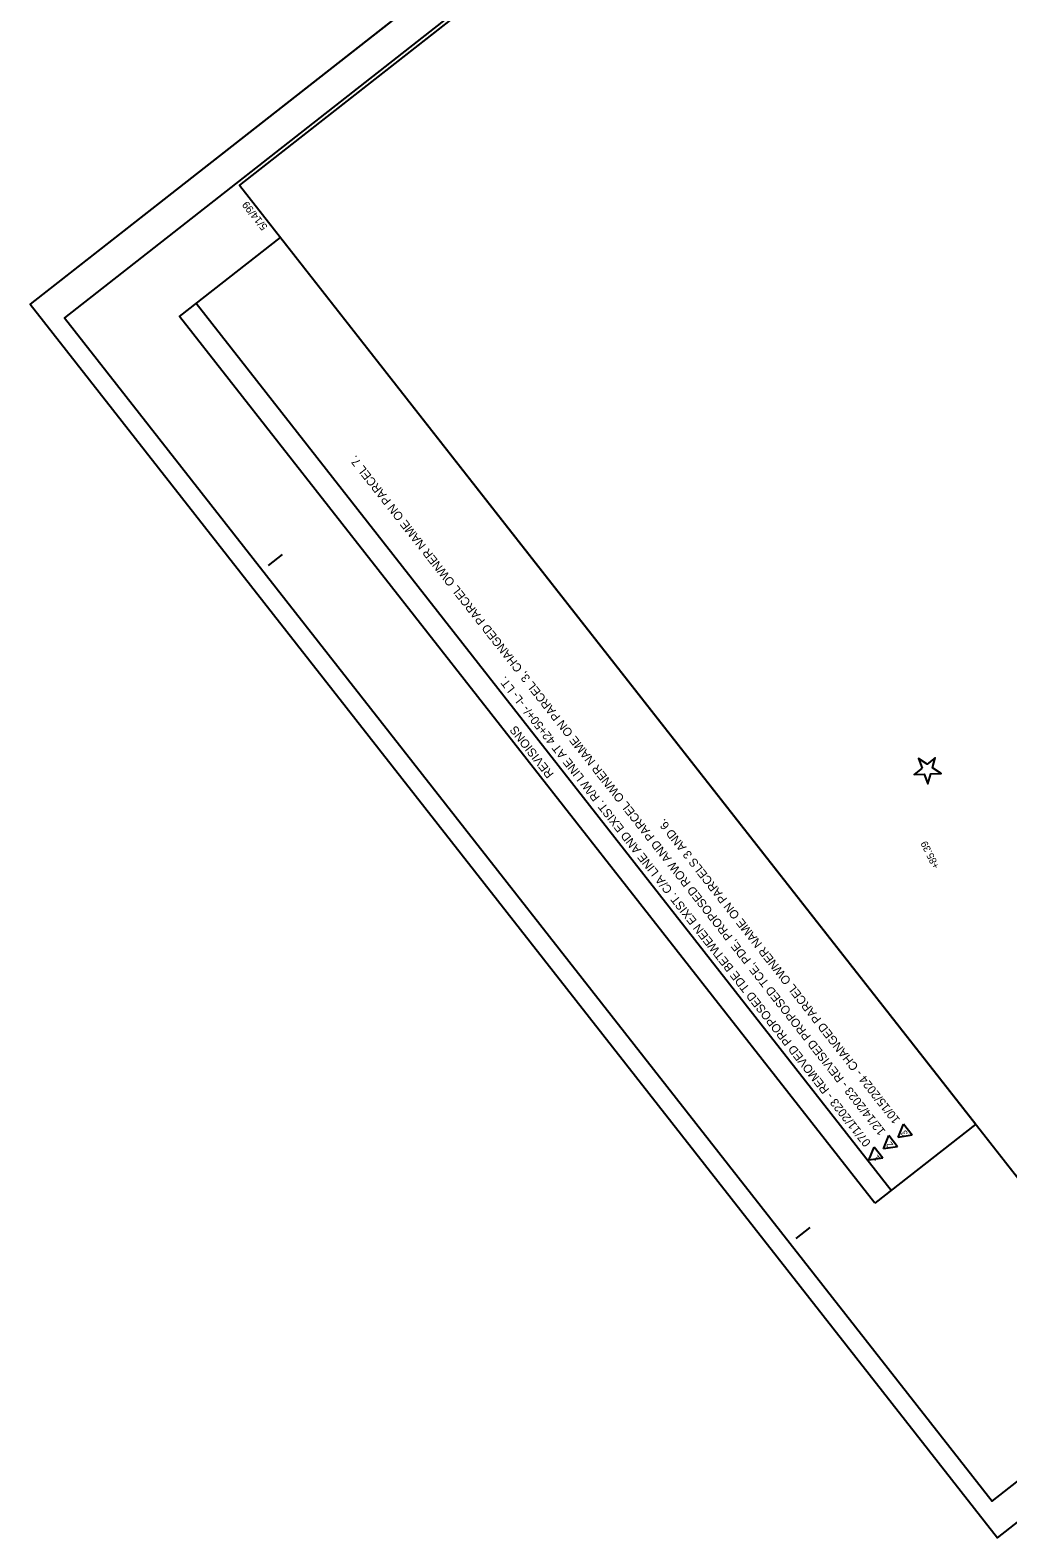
# Model space of a CAD drawing. Extents: x 2174973 to 2176977, y 76106 to 78055.
# Drawn here: x 2174973 to 2175659, y 76106 to 77164 of the extents above; entities that cross this region are included whole.
import ezdxf

# ---------------------------------------------------------------- set-up
doc = ezdxf.new("R2010")
doc.units = 0
for name, color, linetype in [('CTL Primary Horizontal and Vertical CELL', 7, 'Continuous'), ('CTL Primary Horizontal CELL', 7, 'Continuous'), ('CTL Primary Horizontal Cogo Elevation', 7, 'Continuous'), ('CTL Primary Horizontal Cogo Number', 7, 'Continuous'), ('Exist Other Culture Sign Cogo Point CELL', 7, 'Continuous'), ('Exist Property Iron Pin Cogo Comment', 7, 'Continuous'), ('Exist Roads Curbs', 7, 'Continuous'), ('Exist Structure Minor Pipes RCP 18 Inch', 7, 'Continuous')]:
    doc.layers.add(name, color=color, linetype=linetype)

msp = doc.modelspace()

# ---------------------------------------------------------------- linework, layer by layer
at = {"layer": 'CTL Primary Horizontal and Vertical CELL'}
msp.add_lwpolyline([(2175306.6, 76817.1), (2175665.1, 76359.7), (2175813.8, 76476.3), (2175916.7, 76345.1), (2176696.6, 76956.6), (2176763.6, 77051.2), (2176889.6, 77229), (2176824.7, 77311.7), (2176559.2, 77534.4), (2176539.4, 77550.9), (2176367.7, 77694.9), (2176359, 77688.1), (2176301.9, 77760.8), (2176250.3, 77720.3), (2176235.8, 77738.8), (2176166.4, 77827.4), (2176143.2, 77856.9), (2175957.2, 77711.1), (2175525.7, 77372.9), (2175451.3, 77314.6), (2175120.1, 77055)], close=True, dxfattribs=at)
at = {"layer": 'CTL Primary Horizontal CELL'}
msp.add_lwpolyline([(2176308.9, 77990.1), (2174997.3, 76962), (2175648.2, 76131.6), (2176959.8, 77159.7)], close=True, dxfattribs=at)
at = {"layer": 'CTL Primary Horizontal Cogo Elevation'}
for p, q in [((2176298.6, 78010.5), (2174973.3, 76971.6)), ((2175651.9, 76105.9), (2176977.2, 77144.8)), ((2174973.3, 76971.6), (2175651.9, 76105.9))]:
    msp.add_line(p, q, dxfattribs=at)
at = {"layer": 'CTL Primary Horizontal Cogo Number'}
msp.add_lwpolyline([(2176298.6, 78010.5), (2174973.3, 76971.6), (2175651.9, 76105.9), (2176977.2, 77144.8)], close=True, dxfattribs=at)
at = {"layer": 'Exist Other Culture Sign Cogo Point CELL'}
for p, q in [((2175120.9, 77055.6), (2175120.9, 77055.6)), ((2175140.5, 76788.2), (2175150.3, 76796)), ((2175510.6, 76316), (2175520.5, 76323.7))]:
    msp.add_line(p, q, dxfattribs=at)
msp.add_lwpolyline([(2176300.7, 77980.3), (2175120.1, 77055), (2175767.9, 76228.6), (2176948.4, 77154)], close=True, dxfattribs=at)
at = {"layer": 'Exist Property Iron Pin Cogo Comment'}
msp.add_lwpolyline([(2175599, 76646), (2175593.3, 76641.5), (2175600.5, 76641.8), (2175603, 76635), (2175605, 76642), (2175612.3, 76642.2), (2175606.2, 76646.3), (2175608.2, 76653.3), (2175602.5, 76648.8), (2175596.5, 76652.8), (2175599, 76646)], dxfattribs=at)
at = {"layer": 'Exist Structure Minor Pipes RCP 18 Inch'}
for p, q in [((2175577.3, 76349.7), (2175089.6, 76971.9)), ((2175582.1, 76386.9), (2175586, 76396.2)), ((2175592.1, 76388.4), (2175586, 76396.2)), ((2175571.8, 76378.8), (2175575.7, 76388.2)), ((2175581.8, 76380.3), (2175575.7, 76388.2)), ((2175592.1, 76388.4), (2175582.1, 76386.9)), ((2175561.5, 76370.8), (2175565.4, 76380.1)), ((2175571.5, 76372.3), (2175561.5, 76370.8)), ((2175571.5, 76372.3), (2175565.4, 76380.1)), ((2175581.8, 76380.3), (2175571.8, 76378.8))]:
    msp.add_line(p, q, dxfattribs=at)
msp.add_lwpolyline([(2175565.9, 76340.7), (2175078.1, 76962.9), (2175148.8, 77018.4), (2175636.6, 76396.1)], close=True, dxfattribs=at)

# ---------------------------------------------------------------- texts
at = {"layer": 'Exist Other Culture Sign Cogo Point CELL'}
msp.add_text('5/14/99', height=5.25, rotation=128.091, dxfattribs=at).set_placement((2175140.1, 77025.9))
at = {"layer": 'Exist Roads Curbs'}
msp.add_text('+85.39', height=5, rotation=116.2823, dxfattribs=at).set_placement((2175611.3, 76576.9))
at = {"layer": 'Exist Structure Minor Pipes RCP 18 Inch'}
for s, height, p in [('  12/14/2023 - REVISED PROPOSED TCE, PDE, PROPOSED ROW AND PARCEL OWNER NAME ON PARCEL 3, CHANGED PARCEL OWNER NAME ON PARCEL 7.', 6, (2175576.4, 76387.7)), ('  07/11/2023 - REMOVED PROPOSED TDE BETWEEN EXIST. C/A LINE AND EXIST. R/W LINE AT 42+50+/- -L- LT.', 6, (2175566.1, 76379.7)), ('REVISIONS', 6, (2175340.9, 76641.9)), ('  10/15/2024 - CHANGED PARCEL OWNER NAME ON PARCELS 3 AND 6.', 6, (2175586.6, 76395.8)), ('2', 4.5, (2175579, 76381.7)), ('3', 4.5, (2175589.3, 76389.8)), (' 1', 4.5, (2175570.7, 76371.1))]:
    msp.add_text(s, height=height, rotation=128.091, dxfattribs=at).set_placement(p)

doc.saveas('drawing.dxf')
